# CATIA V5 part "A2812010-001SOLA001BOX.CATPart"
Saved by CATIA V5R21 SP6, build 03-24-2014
Part number: A2812010-001SOLA001BOX
Revision: --A
Definition: A2812010-001SOLA001.BOX
Source: made
Description: START_SOLV5_EF2000______
Property "PTC_WM_NAME": "A2812010-001SOLA001.BOX"
Property "PTC_WM_NUMBER": "A2812010-001SOLA001BOX"
Property "PTC_WM_REVISION": "--A"
Property "PTC_WM_INIT_REV": "01"
Bounding box of the stored display mesh (mm): x -40 to 0, y -69.947 to 69.307, z 0 to 147.687
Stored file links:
  J:\Transfer\Fueller Werkstudent\Stellungen\A2812010-001SOLA001BOX.CATPart
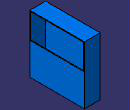
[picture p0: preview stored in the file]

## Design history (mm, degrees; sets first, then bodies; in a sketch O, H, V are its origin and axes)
AxisSystem1: origin (0, 0, 0), X (1, 0, 0), Y (0, 1, 0), Z (0, 0, 1)
Body1 (main body)
  Body2 "Positive"
    Sketch1 on yz-plane, origin (0, 0, 0), H (0, 1, 0), V (0, 0, 1)
      point P1 (-69.9471, 0)
      line L1 (-69.9471, 0) -> (69.3072, 0)
      line L2 (69.3072, 0) -> (69.3072, 147.6873)
      line L3 (69.3072, 147.6873) -> (-69.9471, 147.6873)
      line L4 (-69.9471, 147.6873) -> (-69.9471, 0)
      coincidence: P1 H
      horizontal: L1 H, L3 H
      vertical: L2 V, L4 V
    Pad1: profile Sketch1, direction (-1, 0, 0), length 40
    Body3 "Remove"
      Sketch2 on yz-plane, origin (0, 0, 0), H (0, 1, 0), V (0, 0, 1)
        point P1 (-67.9471, 0)
        line L1 (67.3072, 81.3757) -> (67.3072, 145.6873)
        line L2 (67.3072, 145.6873) -> (-67.9471, 145.6873)
        line L3 (-67.9471, 145.6873) -> (-67.9471, 81.3757)
        line L4 (-67.9471, 81.3757) -> (67.3072, 81.3757)
        distance L1 V = 67.3072
        distance L3 V = 67.9471
        distance L4 H = 81.3757
        distance L2 H = 145.6873
        coincidence: P1 H, P1 L3
        horizontal: L2 H, L4 H
        vertical: L1 V, L3 V
      Pad2: profile Sketch2, direction (-1, 0, 0), length 38, opposite side length 5
    Remove1: tool Body3
    Shell1: ExtOffset 0, Face face of Pad2 from Sketch2.L4, IntOffset 2
  Assemble1: tool Body2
